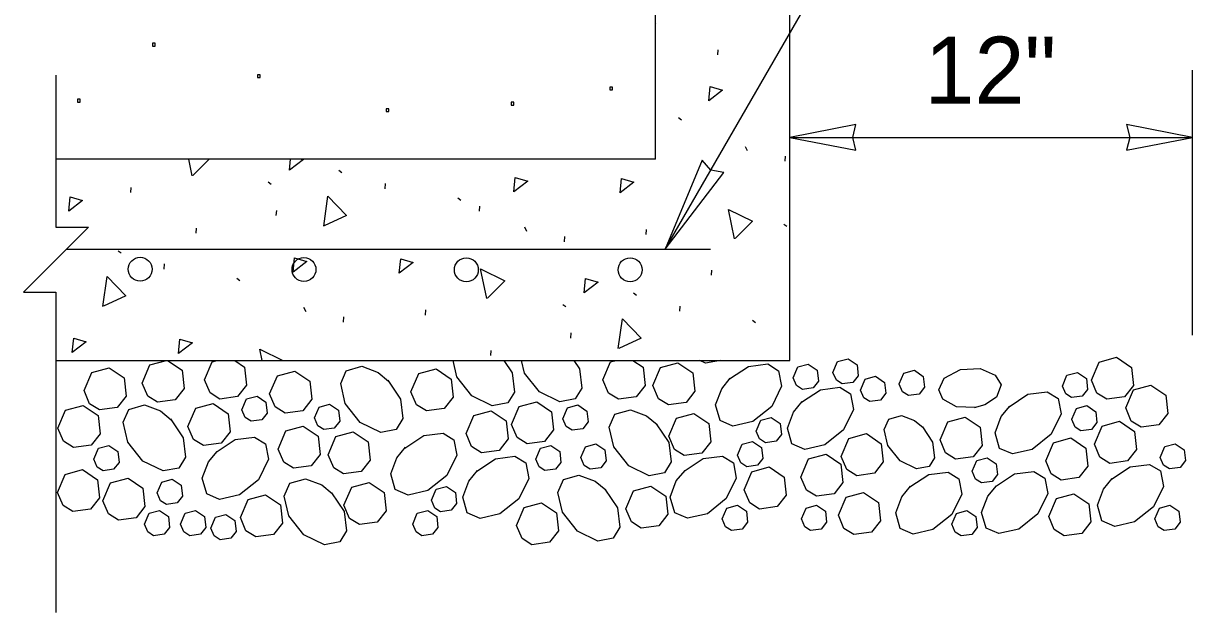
# Model space of a CAD drawing. Extents: x 99862 to 104211, y 98939 to 102076.
# Drawn here: x 101078.5 to 101357.2, y 100191.7 to 100332.1 of the extents above; entities that cross this region are included whole.
import ezdxf

# ---------------------------------------------------------------- set-up
doc = ezdxf.new("R2010")
doc.units = 0
for name, color, linetype in [('Level 1', 7, 'Continuous'), ('Level 15', 7, 'Continuous'), ('Level 17', 7, 'Continuous'), ('Level 18', 7, 'Continuous'), ('Level 19', 7, 'Continuous'), ('Level 20', 7, 'Continuous'), ('Level 23', 7, 'Continuous'), ('Level 7', 7, 'Continuous')]:
    doc.layers.add(name, color=color, linetype=linetype)

msp = doc.modelspace()

# ---------------------------------------------------------------- linework, layer by layer
at = {"layer": 'Level 1'}
for points in [[(101109.96, 100327.39), (101109.3, 100327.39), (101109.3, 100326.73), (101109.96, 100326.73)], [(101135, 100319.89), (101134.34, 100319.89), (101134.34, 100319.23), (101135, 100319.23)], [(101218.96, 100316.93), (101218.3, 100316.93), (101218.3, 100316.27), (101218.96, 100316.27)], [(101092.09, 100314.02), (101091.43, 100314.02), (101091.43, 100313.36), (101092.09, 100313.36)], [(101195.45, 100313.31), (101194.79, 100313.31), (101194.79, 100312.65), (101195.45, 100312.65)], [(101165.66, 100311.74), (101165, 100311.74), (101165, 100311.08), (101165.66, 100311.08)]]:
    msp.add_lwpolyline(points, close=True, dxfattribs=at)
at = {"layer": 'Level 15'}
for p, q in [((101231.47, 100278.27), (101296.65, 100391.16)), ((101357.22, 100257.79), (101357.22, 100320.95)), ((101261.22, 100304.95), (101357.22, 100304.95))]:
    msp.add_line(p, q, dxfattribs=at)
msp.add_lwpolyline([(101086.28, 100319.79), (101086.28, 100283.53), (101094.02, 100283.53), (101078.53, 100268.05), (101086.28, 100268.05), (101086.28, 100191.69)], dxfattribs=at)
for points in [[(101261.22, 100304.95), (101276.94, 100301.87), (101276.21, 100304.95), (101276.94, 100308.03)], [(101357.22, 100304.95), (101341.49, 100308.03), (101342.22, 100304.95), (101341.49, 100301.87)], [(101231.47, 100278.27), (101245.47, 100296.55), (101242.36, 100297.12), (101240.3, 100299.53)]]:
    msp.add_lwpolyline(points, close=True, dxfattribs=at)
at = {"layer": 'Level 17'}
for p, q in [((101229.22, 100299.79), (101229.22, 101853.53)), ((101261.22, 100251.79), (101261.22, 101853.53)), ((101229.22, 100299.79), (101086.28, 100299.79)), ((101086.28, 100251.79), (101261.22, 100251.79))]:
    msp.add_line(p, q, dxfattribs=at)
at = {"layer": 'Level 18'}
msp.add_line((101088.76, 100278.27), (101242.27, 100278.27), dxfattribs=at)
at = {"layer": 'Level 19'}
for p, q in [((101229.22, 100332.12), (101229.27, 100332.01)), ((101244.07, 100324.63), (101244.15, 100325.85)), ((101234.68, 100309.7), (101235.4, 100309.17)), ((101250.57, 100302.8), (101251.07, 100301.79)), ((101260.11, 100299.25), (101260.2, 100300.47)), ((101153.72, 100297.1), (101154.44, 100296.57)), ((101104.15, 100291.81), (101104.23, 100293.03)), ((101136.91, 100294.34), (101137.63, 100293.81)), ((101164.74, 100292.71), (101164.82, 100293.93)), ((101182.06, 100290.55), (101182.78, 100290.02)), ((101138.82, 100286.32), (101138.91, 100287.55)), ((101187.25, 100287.35), (101187.33, 100288.57)), ((101259.75, 100284.3), (101260.47, 100283.77)), ((101119.71, 100282.13), (101119.8, 100283.35)), ((101197.95, 100283.64), (101198.45, 100282.63)), ((101207.49, 100280.09), (101207.57, 100281.31)), ((101226.99, 100281.77), (101227.08, 100282.99)), ((101101.1, 100277.94), (101101.82, 100277.41)), ((101112.11, 100273.56), (101112.2, 100274.78)), ((101242.55, 100272.09), (101242.64, 100273.31)), ((101129.44, 100271.4), (101130.16, 100270.87)), ((101223.94, 100267.9), (101224.66, 100267.37)), ((101207.13, 100265.15), (101207.85, 100264.62)), ((101234.96, 100263.51), (101235.04, 100264.74)), ((101145.33, 100264.49), (101145.83, 100263.48)), ((101154.87, 100260.94), (101154.95, 100262.16)), ((101174.37, 100262.61), (101174.45, 100263.84)), ((101252.28, 100261.35), (101253, 100260.82)), ((101209.04, 100257.13), (101209.13, 100258.35)), ((101189.93, 100252.93), (101190.02, 100254.16))]:
    msp.add_line(p, q, dxfattribs=at)
for points in [[(101241.87, 100313.65), (101242.21, 100317.08), (101245.18, 100316.18), (101241.87, 100313.65)], [(101118.8, 100295.78), (101117.94, 100299.79)], [(101122.85, 100299.79), (101118.9, 100295.85)], [(101141.97, 100297.11), (101142.23, 100299.79)], [(101144.78, 100299.79), (101145.28, 100299.64), (101141.97, 100297.11)], [(101195.43, 100291.98), (101195.77, 100295.41), (101198.75, 100294.51), (101195.43, 100291.98)], [(101220.74, 100291.73), (101221.08, 100295.16), (101224.06, 100294.26), (101220.74, 100291.73)], [(101089.34, 100287.34), (101089.68, 100290.77), (101092.66, 100289.87), (101089.34, 100287.34)], [(101150.11, 100283.82), (101151.1, 100290.92), (101155.55, 100286.33), (101150.23, 100283.86)], [(101248.06, 100280.75), (101246.56, 100287.77), (101252.31, 100284.97), (101248.16, 100280.83)], [(101142.81, 100272.82), (101143.15, 100276.25), (101146.12, 100275.35), (101142.81, 100272.82)], [(101168.12, 100272.58), (101168.46, 100276.01), (101171.43, 100275.11), (101168.12, 100272.58)], [(101189.02, 100266.58), (101187.52, 100273.59), (101193.27, 100270.79), (101189.12, 100266.66)], [(101097.49, 100264.67), (101098.47, 100271.77), (101102.93, 100267.17), (101097.6, 100264.71)], [(101212.19, 100267.91), (101212.53, 100271.34), (101215.5, 100270.44), (101212.19, 100267.91)], [(101220.33, 100254.62), (101221.32, 100261.73), (101225.77, 100257.13), (101220.45, 100254.67)], [(101090.19, 100253.67), (101090.52, 100257.1), (101093.5, 100256.2), (101090.19, 100253.67)], [(101115.5, 100253.43), (101115.84, 100256.86), (101118.81, 100255.95), (101115.5, 100253.43)], [(101135.46, 100251.79), (101134.89, 100254.44), (101140.34, 100251.79)]]:
    msp.add_lwpolyline(points, dxfattribs=at)
at = {"layer": 'Level 23'}
for points in [[(101106.85, 100246.41), (101108.68, 100250.71), (101112.62, 100251.79)], [(101112.91, 100251.79), (101116.39, 100249.44), (101116.87, 100245.11), (101114.73, 100242.4), (101110.53, 100241.82), (101108.17, 100243.29), (101106.85, 100246.41)], [(101121.71, 100247.18), (101123.55, 100251.48), (101124.69, 100251.79)], [(101128.91, 100251.79), (101131.26, 100250.21), (101131.74, 100245.87), (101129.6, 100243.16), (101125.39, 100242.58), (101123.04, 100244.06), (101121.72, 100247.18)], [(101193.06, 100251.79), (101195, 100248.87), (101195.57, 100244.26), (101193.98, 100241.68), (101190.3, 100240.97), (101185.44, 100243.35), (101181.85, 100247.85), (101180.94, 100251.79)], [(101209.77, 100251.79), (101211.1, 100249.79), (101211.67, 100245.19), (101210.09, 100242.61), (101206.4, 100241.9), (101201.54, 100244.27), (101197.95, 100248.78), (101197.26, 100251.79)], [(101216.68, 100247.13), (101218.51, 100251.43), (101219.81, 100251.79)], [(101223.81, 100251.79), (101226.22, 100250.16), (101226.7, 100245.83), (101224.57, 100243.12), (101220.35, 100242.54), (101218, 100244.02), (101216.68, 100247.13)], [(101228.58, 100245.78), (101230.42, 100250.08), (101234.56, 100251.21), (101238.13, 100248.81), (101238.61, 100244.48), (101236.47, 100241.77), (101232.26, 100241.19), (101229.91, 100242.66), (101228.58, 100245.78)], [(101244.66, 100251.79), (101241.12, 100251.11), (101239.73, 100251.79)], [(101246.86, 100247.37), (101251.37, 100250.37), (101255.97, 100250.94), (101258.55, 100249.35), (101259.26, 100245.67), (101256.89, 100240.81), (101252.38, 100237.22), (101247.65, 100236.12), (101244.58, 100237.46), (101243.52, 100241.18), (101244.97, 100245.03), (101247.03, 100247.54)], [(101262.02, 100247.66), (101263.12, 100250.24), (101265.61, 100250.92), (101267.75, 100249.48), (101268.04, 100246.88), (101266.75, 100245.25), (101264.23, 100244.9), (101262.82, 100245.79), (101262.02, 100247.66)], [(101271.5, 100248.94), (101272.6, 100251.52), (101275.09, 100252.2), (101277.23, 100250.75), (101277.52, 100248.15), (101276.23, 100246.53), (101273.71, 100246.18), (101272.3, 100247.07), (101271.5, 100248.94)], [(101333.08, 100247.11), (101334.92, 100251.41), (101339.07, 100252.55), (101342.63, 100250.14), (101343.11, 100245.81), (101340.97, 100243.1), (101336.76, 100242.52), (101334.41, 100243.99), (101333.09, 100247.11)], [(101093, 100244.59), (101094.83, 100248.89), (101098.98, 100250.02), (101102.55, 100247.61), (101103.03, 100243.28), (101100.89, 100240.57), (101096.68, 100239.99), (101094.33, 100241.47), (101093, 100244.59)], [(101137.23, 100243.83), (101139.07, 100248.13), (101143.21, 100249.26), (101146.78, 100246.85), (101147.26, 100242.52), (101145.12, 100239.81), (101140.91, 100239.23), (101138.56, 100240.71), (101137.23, 100243.83)], [(101165.4, 100247.05), (101168.4, 100242.55), (101168.97, 100237.94), (101167.39, 100235.36), (101163.7, 100234.65), (101158.84, 100237.03), (101155.25, 100241.53), (101154.16, 100246.26), (101155.49, 100249.34), (101159.22, 100250.39), (101163.06, 100248.94), (101165.57, 100246.88)], [(101170.92, 100244.34), (101172.76, 100248.64), (101176.9, 100249.77), (101180.47, 100247.36), (101180.95, 100243.03), (101178.81, 100240.32), (101174.6, 100239.74), (101172.25, 100241.22), (101170.92, 100244.34)], [(101278.06, 100244.73), (101279.17, 100247.32), (101281.65, 100248), (101283.79, 100246.55), (101284.08, 100243.95), (101282.8, 100242.33), (101280.27, 100241.98), (101278.86, 100242.87), (101278.07, 100244.74)], [(101287.3, 100246.18), (101288.4, 100248.75), (101290.89, 100249.44), (101293.03, 100247.99), (101293.31, 100245.39), (101292.03, 100243.77), (101289.5, 100243.42), (101288.09, 100244.3), (101287.3, 100246.17)], [(101305.35, 100240.56), (101300.97, 100240.73), (101297.68, 100242.54), (101296.74, 100244.81), (101298.02, 100247.57), (101301.89, 100249.63), (101306.55, 100249.84), (101310.17, 100248.31), (101311.56, 100245.97), (101310.48, 100243.02), (101307.7, 100241.19), (101305.15, 100240.53)], [(101326.17, 100245.68), (101327.27, 100248.26), (101329.76, 100248.94), (101331.89, 100247.49), (101332.18, 100244.9), (101330.9, 100243.27), (101328.37, 100242.92), (101326.96, 100243.81), (101326.17, 100245.68)], [(101263.99, 100241.83), (101268.5, 100244.82), (101273.1, 100245.39), (101275.69, 100243.81), (101276.4, 100240.12), (101274.02, 100235.26), (101269.52, 100231.67), (101264.79, 100230.58), (101261.71, 100231.91), (101260.65, 100235.64), (101262.1, 100239.48), (101264.17, 100241.99)], [(101341.27, 100240.46), (101343.11, 100244.76), (101347.26, 100245.89), (101350.82, 100243.48), (101351.3, 100239.15), (101349.17, 100236.44), (101344.95, 100235.86), (101342.6, 100237.34), (101341.28, 100240.46)], [(101130.64, 100240.04), (101131.74, 100242.62), (101134.23, 100243.3), (101136.36, 100241.86), (101136.65, 100239.26), (101135.37, 100237.63), (101132.84, 100237.29), (101131.43, 100238.17), (101130.64, 100240.04)], [(101313.47, 100240.74), (101317.98, 100243.74), (101322.58, 100244.31), (101325.16, 100242.72), (101325.88, 100239.04), (101323.5, 100234.18), (101319, 100230.59), (101314.27, 100229.49), (101311.19, 100230.83), (101310.13, 100234.55), (101311.58, 100238.4), (101313.65, 100240.91)], [(101086.77, 100235.62), (101088.61, 100239.93), (101092.76, 100241.06), (101096.32, 100238.65), (101096.8, 100234.32), (101094.66, 100231.61), (101090.45, 100231.03), (101088.1, 100232.51), (101086.78, 100235.63)], [(101113.59, 100237.84), (101116.58, 100233.34), (101117.15, 100228.74), (101115.57, 100226.15), (101111.88, 100225.44), (101107.02, 100227.82), (101103.43, 100232.32), (101102.34, 100237.05), (101103.67, 100240.13), (101107.4, 100241.19), (101111.24, 100239.74), (101113.75, 100237.67)], [(101117.77, 100236.08), (101119.6, 100240.38), (101123.75, 100241.51), (101127.32, 100239.1), (101127.8, 100234.77), (101125.66, 100232.06), (101121.45, 100231.48), (101119.1, 100232.96), (101117.77, 100236.08)], [(101147.9, 100238.08), (101149, 100240.66), (101151.49, 100241.34), (101153.63, 100239.9), (101153.92, 100237.3), (101152.63, 100235.67), (101150.11, 100235.33), (101148.7, 100236.21), (101147.9, 100238.08)], [(101184.04, 100234.38), (101185.87, 100238.68), (101190.02, 100239.81), (101193.59, 100237.4), (101194.07, 100233.07), (101191.93, 100230.36), (101187.72, 100229.78), (101185.37, 100231.26), (101184.04, 100234.37)], [(101194.9, 100236.52), (101196.73, 100240.82), (101200.88, 100241.95), (101204.44, 100239.54), (101204.92, 100235.21), (101202.78, 100232.5), (101198.57, 100231.92), (101196.22, 100233.4), (101194.9, 100236.52)], [(101207.11, 100237.91), (101208.21, 100240.48), (101210.7, 100241.17), (101212.84, 100239.72), (101213.12, 100237.12), (101211.84, 100235.5), (101209.32, 100235.15), (101207.9, 100236.03), (101207.11, 100237.9)], [(101229.39, 100236.71), (101232.39, 100232.2), (101232.96, 100227.6), (101231.38, 100225.01), (101227.69, 100224.3), (101222.83, 100226.68), (101219.24, 100231.18), (101218.15, 100235.91), (101219.48, 100238.99), (101223.21, 100240.05), (101227.05, 100238.6), (101229.56, 100236.53)], [(101328.4, 100237.76), (101329.51, 100240.33), (101332, 100241.01), (101334.13, 100239.57), (101334.42, 100236.97), (101333.14, 100235.35), (101330.61, 100235), (101329.2, 100235.88), (101328.41, 100237.75)], [(101232.37, 100233.72), (101234.2, 100238.02), (101238.35, 100239.15), (101241.91, 100236.75), (101242.39, 100232.41), (101240.26, 100229.71), (101236.05, 100229.12), (101233.69, 100230.6), (101232.37, 100233.72)], [(101253.2, 100234.94), (101254.3, 100237.52), (101256.79, 100238.2), (101258.93, 100236.76), (101259.22, 100234.16), (101257.94, 100232.53), (101255.41, 100232.18), (101254, 100233.07), (101253.21, 100234.94)], [(101292.82, 100235.97), (101295.25, 100232.32), (101295.71, 100228.6), (101294.42, 100226.5), (101291.44, 100225.93), (101287.5, 100227.85), (101284.6, 100231.5), (101283.71, 100235.33), (101284.79, 100237.82), (101287.81, 100238.68), (101290.92, 100237.51), (101292.96, 100235.84)], [(101297.02, 100232.85), (101298.85, 100237.15), (101303, 100238.28), (101306.56, 100235.87), (101307.04, 100231.54), (101304.91, 100228.83), (101300.7, 100228.25), (101298.34, 100229.73), (101297.02, 100232.85)], [(101333.81, 100231.84), (101335.64, 100236.14), (101339.79, 100237.28), (101343.35, 100234.87), (101343.83, 100230.54), (101341.7, 100227.83), (101337.49, 100227.25), (101335.13, 100228.72), (101333.81, 100231.84)], [(101139.26, 100230.68), (101141.09, 100234.98), (101145.24, 100236.11), (101148.8, 100233.7), (101149.28, 100229.37), (101147.15, 100226.66), (101142.94, 100226.08), (101140.58, 100227.56), (101139.26, 100230.68)], [(101151.16, 100229.33), (101153, 100233.63), (101157.14, 100234.76), (101160.71, 100232.35), (101161.19, 100228.02), (101159.05, 100225.31), (101154.84, 100224.73), (101152.49, 100226.21), (101151.16, 100229.32)], [(101169.44, 100230.91), (101173.95, 100233.91), (101178.55, 100234.48), (101181.13, 100232.9), (101181.84, 100229.21), (101179.47, 100224.35), (101174.97, 100220.76), (101170.24, 100219.67), (101167.16, 100221), (101166.1, 100224.73), (101167.55, 100228.57), (101169.61, 100231.08)], [(101273.48, 100228.91), (101275.31, 100233.21), (101279.46, 100234.35), (101283.02, 100231.94), (101283.5, 100227.61), (101281.36, 100224.9), (101277.15, 100224.32), (101274.8, 100225.8), (101273.48, 100228.91)], [(101095.32, 100228.27), (101096.42, 100230.84), (101098.91, 100231.53), (101101.05, 100230.08), (101101.33, 100227.48), (101100.05, 100225.86), (101097.53, 100225.51), (101096.11, 100226.39), (101095.32, 100228.26)], [(101124.51, 100229.93), (101129.02, 100232.93), (101133.62, 100233.5), (101136.21, 100231.91), (101136.92, 100228.23), (101134.54, 100223.37), (101130.04, 100219.78), (101125.31, 100218.68), (101122.23, 100220.02), (101121.17, 100223.74), (101122.62, 100227.59), (101124.69, 100230.1)], [(101200.65, 100228.28), (101201.75, 100230.86), (101204.24, 100231.54), (101206.37, 100230.1), (101206.66, 100227.5), (101205.38, 100225.87), (101202.85, 100225.52), (101201.44, 100226.41), (101200.65, 100228.28)], [(101211.4, 100228.63), (101212.5, 100231.21), (101214.99, 100231.89), (101217.13, 100230.45), (101217.42, 100227.85), (101216.14, 100226.22), (101213.61, 100225.88), (101212.2, 100226.76), (101211.4, 100228.63)], [(101248.75, 100229.22), (101249.85, 100231.8), (101252.34, 100232.48), (101254.47, 100231.04), (101254.76, 100228.44), (101253.48, 100226.81), (101250.95, 100226.47), (101249.54, 100227.35), (101248.75, 100229.22)], [(101322.2, 100227.88), (101324.03, 100232.18), (101328.18, 100233.31), (101331.74, 100230.9), (101332.22, 100226.57), (101330.09, 100223.86), (101325.87, 100223.28), (101323.52, 100224.76), (101322.2, 100227.88)], [(101349.5, 100228.69), (101350.6, 100231.27), (101353.09, 100231.95), (101355.23, 100230.51), (101355.52, 100227.91), (101354.23, 100226.28), (101351.71, 100225.93), (101350.3, 100226.82), (101349.5, 100228.69)], [(101186.58, 100225.37), (101191.08, 100228.37), (101195.68, 100228.94), (101198.27, 100227.35), (101198.98, 100223.67), (101196.6, 100218.81), (101192.1, 100215.22), (101187.37, 100214.12), (101184.29, 100215.45), (101183.24, 100219.18), (101184.68, 100223.03), (101186.75, 100225.54)], [(101236.05, 100225.41), (101240.56, 100228.41), (101245.16, 100228.98), (101247.75, 100227.39), (101248.46, 100223.71), (101246.08, 100218.85), (101241.58, 100215.26), (101236.85, 100214.16), (101233.77, 100215.49), (101232.71, 100219.22), (101234.16, 100223.07), (101236.23, 100225.58)], [(101263.86, 100224), (101265.69, 100228.3), (101269.84, 100229.43), (101273.4, 100227.03), (101273.88, 100222.7), (101271.75, 100219.99), (101267.54, 100219.41), (101265.18, 100220.88), (101263.86, 100224)], [(101304.69, 100225.36), (101305.79, 100227.94), (101308.28, 100228.61), (101310.41, 100227.17), (101310.7, 100224.57), (101309.42, 100222.95), (101306.89, 100222.6), (101305.48, 100223.49), (101304.69, 100225.36)], [(101086.68, 100220.34), (101088.51, 100224.64), (101092.66, 100225.78), (101096.23, 100223.37), (101096.7, 100219.04), (101094.57, 100216.33), (101090.36, 100215.75), (101088.01, 100217.23), (101086.68, 100220.34)], [(101250.32, 100220.96), (101252.15, 100225.26), (101256.3, 100226.4), (101259.87, 100223.99), (101260.34, 100219.66), (101258.21, 100216.95), (101254, 100216.37), (101251.65, 100217.84), (101250.32, 100220.96)], [(101337.85, 100223.46), (101342.35, 100226.45), (101346.96, 100227.02), (101349.54, 100225.44), (101350.25, 100221.76), (101347.88, 100216.9), (101343.37, 100213.3), (101338.64, 100212.21), (101335.56, 100213.54), (101334.51, 100217.27), (101335.96, 100221.12), (101338.02, 100223.63)], [(101097.49, 100218.3), (101099.33, 100222.6), (101103.48, 100223.74), (101107.04, 100221.33), (101107.52, 100217), (101105.38, 100214.29), (101101.17, 100213.71), (101098.82, 100215.19), (101097.5, 100218.3)], [(101110.42, 100220.23), (101111.52, 100222.81), (101114.01, 100223.49), (101116.15, 100222.05), (101116.44, 100219.45), (101115.15, 100217.82), (101112.63, 100217.48), (101111.22, 100218.36), (101110.42, 100220.23)], [(101151.98, 100220.25), (101154.97, 100215.75), (101155.54, 100211.14), (101153.96, 100208.56), (101150.27, 100207.85), (101145.41, 100210.22), (101141.82, 100214.73), (101140.73, 100219.46), (101142.06, 100222.53), (101145.79, 100223.59), (101149.64, 100222.14), (101152.14, 100220.08)], [(101217.15, 100221.13), (101220.15, 100216.62), (101220.72, 100212.02), (101219.13, 100209.44), (101215.45, 100208.73), (101210.59, 100211.1), (101207, 100215.61), (101205.9, 100220.34), (101207.24, 100223.41), (101210.96, 100224.47), (101214.81, 100223.02), (101217.32, 100220.96)], [(101289.81, 100221.63), (101294.31, 100224.62), (101298.92, 100225.19), (101301.5, 100223.61), (101302.21, 100219.93), (101299.84, 100215.06), (101295.33, 100211.47), (101290.6, 100210.38), (101287.52, 100211.71), (101286.47, 100215.44), (101287.92, 100219.29), (101289.98, 100221.79)], [(101310.27, 100221.75), (101314.78, 100224.75), (101319.38, 100225.32), (101321.96, 100223.73), (101322.67, 100220.05), (101320.3, 100215.19), (101315.8, 100211.6), (101311.06, 100210.51), (101307.99, 100211.84), (101306.93, 100215.57), (101308.38, 100219.41), (101310.44, 100221.92)], [(101154.95, 100217.26), (101156.78, 100221.56), (101160.93, 100222.7), (101164.49, 100220.29), (101164.97, 100215.96), (101162.84, 100213.25), (101158.63, 100212.67), (101156.27, 100214.14), (101154.95, 100217.26)], [(101175.78, 100218.48), (101176.89, 100221.07), (101179.38, 100221.74), (101181.51, 100220.3), (101181.8, 100217.7), (101180.52, 100216.08), (101177.99, 100215.73), (101176.58, 100216.61), (101175.79, 100218.48)], [(101222.11, 100216.42), (101223.95, 100220.72), (101228.1, 100221.85), (101231.66, 100219.44), (101232.14, 100215.11), (101230, 100212.4), (101225.79, 100211.82), (101223.44, 100213.3), (101222.11, 100216.42)], [(101272.79, 100214.88), (101274.63, 100219.18), (101278.78, 100220.32), (101282.34, 100217.91), (101282.82, 100213.58), (101280.68, 100210.87), (101276.47, 100210.29), (101274.12, 100211.76), (101272.8, 100214.88)], [(101322.91, 100214.59), (101324.74, 100218.9), (101328.89, 100220.03), (101332.45, 100217.62), (101332.93, 100213.29), (101330.8, 100210.58), (101326.59, 100210), (101324.23, 100211.48), (101322.91, 100214.59)], [(101130.26, 100214.32), (101132.09, 100218.63), (101136.24, 100219.76), (101139.8, 100217.35), (101140.28, 100213.02), (101138.15, 100210.31), (101133.94, 100209.73), (101131.58, 100211.21), (101130.26, 100214.32)], [(101196.06, 100212.46), (101197.89, 100216.76), (101202.04, 100217.89), (101205.6, 100215.48), (101206.08, 100211.15), (101203.95, 100208.44), (101199.74, 100207.86), (101197.38, 100209.34), (101196.06, 100212.46)], [(101245.12, 100214.02), (101246.22, 100216.6), (101248.71, 100217.28), (101250.85, 100215.84), (101251.13, 100213.24), (101249.85, 100211.61), (101247.33, 100211.26), (101245.91, 100212.15), (101245.12, 100214.02)], [(101263.97, 100214.02), (101265.07, 100216.6), (101267.56, 100217.28), (101269.7, 100215.84), (101269.98, 100213.24), (101268.7, 100211.61), (101266.17, 100211.26), (101264.76, 100212.15), (101263.97, 100214.02)], [(101348.22, 100214.02), (101349.32, 100216.6), (101351.81, 100217.28), (101353.95, 100215.84), (101354.23, 100213.24), (101352.95, 100211.61), (101350.42, 100211.26), (101349.01, 100212.15), (101348.22, 100214.02)], [(101107.37, 100212.77), (101108.48, 100215.35), (101110.96, 100216.03), (101113.1, 100214.58), (101113.39, 100211.98), (101112.11, 100210.36), (101109.58, 100210.01), (101108.17, 100210.9), (101107.38, 100212.77)], [(101115.99, 100212.77), (101117.09, 100215.35), (101119.58, 100216.03), (101121.72, 100214.58), (101122.01, 100211.98), (101120.73, 100210.36), (101118.2, 100210.01), (101116.79, 100210.9), (101116, 100212.77)], [(101123.23, 100211.82), (101124.33, 100214.4), (101126.82, 100215.08), (101128.95, 100213.64), (101129.24, 100211.04), (101127.96, 100209.41), (101125.43, 100209.07), (101124.02, 100209.95), (101123.23, 100211.82)], [(101171.33, 100212.77), (101172.43, 100215.35), (101174.92, 100216.03), (101177.06, 100214.58), (101177.34, 100211.98), (101176.06, 100210.36), (101173.54, 100210.01), (101172.12, 100210.9), (101171.33, 100212.77)], [(101299.84, 100212.75), (101300.94, 100215.33), (101303.43, 100216.01), (101305.57, 100214.56), (101305.86, 100211.97), (101304.58, 100210.34), (101302.05, 100209.99), (101300.64, 100210.88), (101299.85, 100212.75)]]:
    msp.add_lwpolyline(points, dxfattribs=at)
at = {"layer": 'Level 7'}
for centre in [(101106.36, 100273.52), (101145.41, 100273.46), (101184.11, 100273.4), (101223.14, 100273.4)]:
    msp.add_circle(centre, 2.85, dxfattribs=at)

# ---------------------------------------------------------------- texts
at = {"layer": 'Level 20'}
msp.add_text('12"', height=16, dxfattribs=at).set_placement((101293.34, 100312.95))

doc.saveas('drawing.dxf')
